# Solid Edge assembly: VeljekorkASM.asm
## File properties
Author: KULL
Template: Iso Metric Assembly.asm
Last saved by: KULL
Revision: 4
Application: Solid Edge
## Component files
rehvikork.par
rehvikork_logo.par
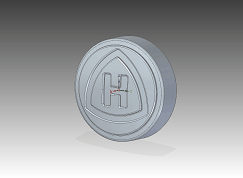
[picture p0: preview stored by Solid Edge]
